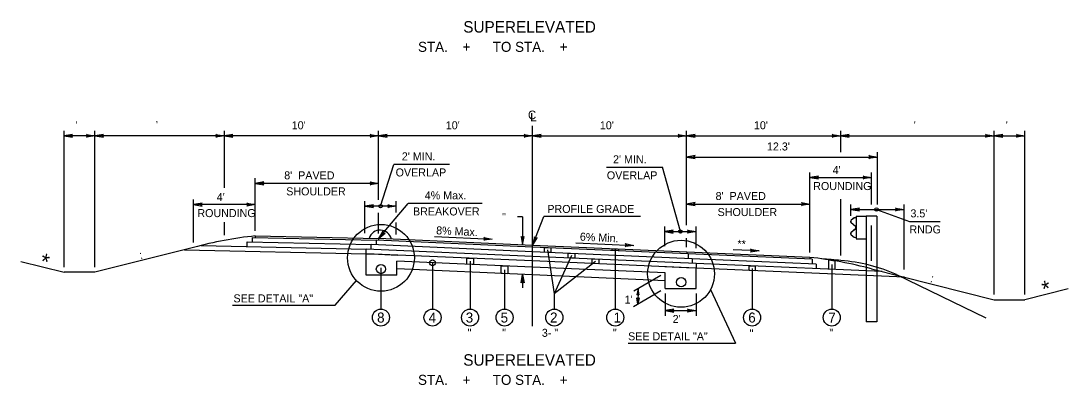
# Model space of a CAD drawing. Extents: x -592 to 1199, y -590 to 416.
# Drawn here: x 459.1 to 642.2, y 44 to 107.5 of the extents above; entities that cross this region are included whole.
import ezdxf

# ---------------------------------------------------------------- set-up
doc = ezdxf.new("R2010")
doc.units = 0
doc.layers.add('1', color=7, linetype='Continuous')
doc.layers.add('Des_ Drain_ Ftrs', color=7, linetype='Continuous')

msp = doc.modelspace()

# ---------------------------------------------------------------- linework, layer by layer
at = {"layer": '1'}
for p, q in [((466.61, 64.54), (466.61, 88.33)), ((471.99, 64.54), (471.99, 88.33)), ((494.66, 78.36), (494.66, 88.33)), ((521.6, 76.29), (521.6, 88.33)), ((548.54, 54.25), (548.54, 89.21)), ((575.48, 71.87), (575.48, 88.33)), ((602.42, 84.63), (602.42, 88.33)), ((629.25, 59.73), (629.25, 88.33)), ((634.64, 59.73), (634.64, 88.33)), ((471.99, 87.45), (466.61, 87.45)), ((494.66, 87.45), (471.99, 87.45)), ((521.6, 87.45), (494.66, 87.45)), ((548.54, 87.45), (521.6, 87.45)), ((548.54, 87.45), (575.48, 87.45)), ((575.48, 87.45), (602.42, 87.45)), ((602.42, 87.45), (629.25, 87.45)), ((629.25, 87.45), (634.64, 87.45)), ((608.85, 75.47), (608.85, 84.63)), ((521.97, 75.17), (524.25, 82.47)), ((534.01, 82.47), (524.25, 82.47)), ((575.48, 83.75), (608.85, 83.75)), ((561.49, 81.96), (571.25, 81.96)), ((574.38, 70.74), (571.25, 81.96)), ((597.04, 67.1), (597.04, 81.05)), ((607.81, 75.47), (607.81, 81.05)), ((500.05, 70.87), (500.05, 80.04)), ((521.6, 79.16), (500.05, 79.16)), ((597.04, 80.17), (607.81, 80.17)), ((489.27, 68.86), (489.27, 76.33)), ((500.05, 75.45), (489.27, 75.45)), ((519.23, 70.45), (519.23, 76.05)), ((524.71, 75.17), (519.23, 75.17)), ((521.59, 69.52), (526.78, 75.66)), ((524.71, 74.1), (524.71, 76.05)), ((539.71, 75.66), (526.78, 75.66)), ((575.48, 75.55), (597.04, 75.55)), ((602.42, 66.56), (602.42, 76.38)), ((604.16, 73.52), (604.16, 75.47)), ((613.54, 64.11), (613.54, 75.47)), ((521.6, 70.4), (521.6, 74.04)), ((546.79, 73.3), (545.91, 73.3)), ((546.79, 73.3), (546.79, 68.42)), ((548.55, 68.33), (550.51, 73.4)), ((567.42, 73.4), (550.51, 73.4)), ((604.16, 74.59), (613.54, 74.59)), ((605.11, 73.41), (605.11, 69.48)), ((605.11, 73.41), (606.85, 73.41)), ((606.85, 73.41), (606.85, 55.01)), ((608.75, 73.41), (606.85, 73.41)), ((608.68, 74.59), (614.44, 72.52)), ((608.75, 73.41), (608.75, 55.01)), ((494.66, 70.09), (494.66, 72.38)), ((524.71, 70.26), (524.71, 72.32)), ((571.64, 68.21), (571.64, 71.62)), ((577.12, 67.83), (577.12, 71.62)), ((604.23, 72.3), (604.99, 71.67)), ((604.78, 73.12), (604.24, 72.73)), ((604.25, 72.32), (605.01, 71.69)), ((604.79, 73.1), (604.26, 72.71)), ((605.11, 73.18), (604.78, 73.12)), ((605.11, 73.15), (604.79, 73.1)), ((605.08, 71.48), (605.08, 71.4)), ((605.11, 71.48), (605.11, 71.4)), ((607.81, 65.65), (607.81, 71.8)), ((614.44, 72.52), (619.79, 72.52)), ((499.55, 69.7), (521.25, 69.23)), ((499.55, 68.92), (499.55, 69.7)), ((500.05, 69.99), (521.59, 69.52)), ((500.05, 69.99), (500.05, 69.69)), ((531.37, 69.86), (541.48, 69.41)), ((571.64, 70.74), (577.12, 70.74)), ((575.48, 68.04), (575.48, 69.61)), ((604.99, 71.22), (604.23, 70.58)), ((604.24, 70.15), (604.78, 69.76)), ((605.01, 71.19), (604.25, 70.56)), ((604.26, 70.17), (604.79, 69.79)), ((604.78, 69.76), (605.11, 69.7)), ((604.79, 69.79), (605.11, 69.73)), ((489.27, 67.98), (471.99, 63.66)), ((490.6, 68.32), (519.41, 67.69)), ((498.63, 68.94), (520.33, 68.46)), ((498.63, 68.15), (498.63, 68.94)), ((548.54, 67.23), (520.33, 68.46)), ((520.33, 67.65), (520.33, 68.46)), ((548.54, 68.04), (521.25, 69.23)), ((521.25, 68.42), (521.25, 69.23)), ((548.54, 68.34), (521.59, 69.52)), ((521.59, 69.52), (521.59, 69.22)), ((575.49, 67.16), (548.54, 68.34)), ((575.72, 66.85), (548.54, 68.04)), ((556.11, 68.77), (566.22, 68.33)), ((605.11, 69.48), (606.85, 69.48)), ((487.68, 67.58), (519.41, 66.88)), ((548.54, 66.42), (519.41, 67.69)), ((519.41, 66.88), (519.41, 67.69)), ((519.41, 63.13), (519.41, 66.88)), ((548.54, 65.61), (519.41, 66.88)), ((519.41, 66.88), (521.6, 66.79)), ((521.6, 66.79), (524.89, 66.65)), ((576.43, 66.01), (548.54, 67.23)), ((577.13, 65.17), (548.54, 66.42)), ((551.17, 67.53), (552.34, 59.9)), ((555.35, 66.55), (552.34, 59.9)), ((563, 67.55), (563, 57.22)), ((597.04, 66.22), (575.49, 67.16)), ((575.49, 67.16), (575.49, 66.86)), ((597.43, 65.91), (575.72, 66.85)), ((575.72, 66.85), (575.72, 66.04)), ((598.13, 65.07), (576.43, 66.01)), ((576.43, 66.01), (576.43, 65.2)), ((588.13, 67.36), (583.64, 67.55)), ((597.04, 66.22), (597.04, 65.92)), ((459.07, 65.54), (466.61, 63.66)), ((522.02, 64.44), (522.02, 57.22)), ((522.03, 64.44), (522.03, 64.44)), ((548.54, 64.53), (524.8, 65.57)), ((524.8, 63.13), (524.8, 65.57)), ((548.54, 63.19), (524.8, 64.22)), ((531.04, 65.3), (531.04, 57.22)), ((537.6, 65.55), (537.6, 57.22)), ((577.13, 64.36), (548.54, 65.61)), ((571.74, 63.52), (548.54, 64.53)), ((559.53, 65.53), (552.34, 59.9)), ((575.48, 64.44), (571.64, 64.6)), ((577.13, 64.36), (575.48, 64.44)), ((577.13, 65.17), (577.13, 64.36)), ((609.65, 63.75), (577.13, 65.17)), ((577.13, 60.83), (577.13, 64.36)), ((613.57, 62.77), (577.13, 64.36)), ((586.92, 64.3), (586.92, 57.22)), ((597.43, 65.91), (597.43, 65.1)), ((598.13, 65.07), (598.13, 64.26)), ((600.85, 64.97), (600.85, 57.22)), ((604.16, 65.46), (604.16, 65.46)), ((607.81, 64.21), (629.25, 58.85)), ((471.99, 63.66), (466.61, 63.66)), ((524.8, 63.13), (519.41, 63.13)), ((543.64, 64.08), (543.64, 57.22)), ((546.79, 63.26), (546.79, 60.9)), ((571.74, 62.17), (548.54, 63.19)), ((570.98, 63.08), (566.22, 60.33)), ((571.74, 60.83), (571.74, 63.52)), ((571.74, 63.52), (571.74, 63.52)), ((612.16, 63.23), (627.78, 55.7)), ((513.99, 57.88), (517.73, 62.2)), ((566.98, 60.77), (566.96, 58.07)), ((571.74, 60.83), (577.13, 60.83)), ((579.66, 60.65), (584.01, 51.25)), ((642.17, 60.74), (634.64, 58.85)), ((552.34, 59.9), (552.34, 57.22)), ((570.98, 60.39), (566.21, 57.63)), ((571.74, 59.95), (571.74, 56.06)), ((577.13, 59.95), (577.13, 56.06)), ((629.25, 58.85), (634.64, 58.85)), ((496.06, 57.88), (513.99, 57.88)), ((571.74, 56.94), (577.13, 56.94)), ((608.75, 55.01), (606.85, 55.01)), ((565.23, 51.25), (584.01, 51.25))]:
    msp.add_line(p, q, dxfattribs=at)
for points in [[(550.6, 67.95), (551.75, 67.9), (551.75, 67.09), (550.6, 67.14)], [(537.03, 66.12), (538.18, 66.07), (538.18, 64.99), (537.03, 65.04)], [(554.78, 66.96), (555.92, 66.91), (555.92, 66.1), (554.78, 66.15)], [(560.1, 65.92), (560.1, 65.11), (558.95, 65.16), (558.95, 65.97)], [(562.43, 67.73), (563.57, 67.68), (563.57, 67.38), (562.43, 67.43)], [(543.07, 64.77), (544.21, 64.72), (544.21, 63.38), (543.07, 63.43)], [(586.4, 64.77), (587.44, 64.72), (587.44, 63.91), (586.4, 63.96)], [(600.33, 65.8), (601.38, 65.63), (601.38, 64.11), (600.33, 64.16)]]:
    msp.add_lwpolyline(points, close=True, dxfattribs=at)
for centre, radius in [((521.97, 75.17), 0.3), ((522.02, 66.16), 5.84), ((574.38, 70.74), 0.3), ((574.5, 63.38), 5.84), ((522.02, 64.2), 0.808), ((531.04, 65.3), 0.5), ((574.52, 61.9), 0.808), ((522.02, 55.73), 1.49), ((531.04, 55.73), 1.49), ((537.6, 55.73), 1.49), ((543.64, 55.73), 1.49), ((552.34, 55.73), 1.49), ((563, 55.73), 1.49), ((586.92, 55.73), 1.49), ((600.85, 55.73), 1.49)]:
    msp.add_circle(centre, radius, dxfattribs=at)
for centre, radius, start, end in [((506.94, 3.15), 67.19, 95.8911, 105.2497), ((521.89, 69), 2, 12.0711, 163.8353), ((590.15, -0.61), 67.19, 74.7602, 84.1188)]:
    msp.add_arc(centre, radius, start, end, dxfattribs=at)
msp.add_ellipse((608.68, 74.59), major_axis=(-0.311, 0), ratio=0.964041, dxfattribs=at)
for centre, major_axis, start_param, end_param in [((604.42, 72.51), (-0.288, 0), 5.35781, 7.138763), ((604.42, 72.51), (-0.258, 0), 5.35781, 7.138763), ((604.82, 71.48), (0.258, 0), 0, 0.855848), ((604.82, 71.48), (0.288, 0), 0, 0.855848), ((604.42, 70.37), (-0.288, 0), 5.427608, 7.208561), ((604.42, 70.37), (-0.258, 0), 5.427608, 7.208561), ((604.82, 71.4), (0.258, 0), 5.427337, 6.283185), ((604.82, 71.4), (0.288, 0), 5.427337, 6.283185), ((591.2, -34.98), (105.02, 0), 1.463691, 1.495354), ((600.23, 38.4), (28.39, 0), 1.136862, 1.493152)]:
    msp.add_ellipse(centre, major_axis=major_axis, ratio=0.964041, start_param=start_param, end_param=end_param, dxfattribs=at)
at = {"layer": 'Des_ Drain_ Ftrs'}
for points in [[(466.61, 87.45), (468.09, 87.2), (467.8, 87.45), (468.09, 87.7)], [(471.99, 87.45), (470.51, 87.2), (470.8, 87.45), (470.51, 87.7)], [(471.99, 87.45), (473.48, 87.2), (473.19, 87.45), (473.48, 87.7)], [(494.66, 87.45), (493.17, 87.2), (493.47, 87.45), (493.17, 87.7)], [(494.66, 87.45), (496.15, 87.2), (495.85, 87.45), (496.15, 87.7)], [(521.6, 87.45), (520.11, 87.2), (520.41, 87.45), (520.11, 87.7)], [(521.6, 87.45), (523.09, 87.2), (522.79, 87.45), (523.09, 87.7)], [(548.54, 87.45), (547.05, 87.2), (547.35, 87.45), (547.05, 87.7)], [(548.54, 87.45), (550.03, 87.2), (549.74, 87.45), (550.03, 87.7)], [(575.48, 87.45), (573.99, 87.2), (574.29, 87.45), (573.99, 87.7)], [(575.48, 87.45), (576.97, 87.2), (576.68, 87.45), (576.97, 87.7)], [(602.42, 87.45), (600.94, 87.2), (601.23, 87.45), (600.94, 87.7)], [(602.42, 87.45), (603.91, 87.2), (603.62, 87.45), (603.91, 87.7)], [(629.25, 87.45), (627.76, 87.2), (628.05, 87.45), (627.76, 87.7)], [(629.25, 87.45), (630.74, 87.2), (630.44, 87.45), (630.74, 87.7)], [(634.64, 87.45), (633.15, 87.2), (633.44, 87.45), (633.15, 87.7)], [(575.48, 83.75), (576.97, 83.5), (576.68, 83.75), (576.97, 84)], [(608.85, 83.75), (607.36, 83.5), (607.66, 83.75), (607.36, 84)], [(500.05, 79.16), (501.54, 78.91), (501.24, 79.16), (501.54, 79.41)], [(521.6, 79.16), (520.11, 78.91), (520.41, 79.16), (520.11, 79.41)], [(597.04, 80.17), (598.52, 79.93), (598.23, 80.17), (598.52, 80.42)], [(607.81, 80.17), (606.32, 79.93), (606.62, 80.17), (606.32, 80.42)], [(489.27, 75.45), (490.76, 75.2), (490.46, 75.45), (490.76, 75.7)], [(500.05, 75.45), (498.56, 75.2), (498.85, 75.45), (498.56, 75.7)], [(519.23, 75.17), (520.71, 74.92), (520.42, 75.17), (520.71, 75.41)], [(524.71, 75.17), (523.22, 74.92), (523.52, 75.17), (523.22, 75.41)], [(575.48, 75.55), (576.97, 75.3), (576.68, 75.55), (576.97, 75.79)], [(597.04, 75.55), (595.55, 75.3), (595.84, 75.55), (595.55, 75.79)], [(604.16, 74.59), (605.7, 74.34), (605.4, 74.59), (605.7, 74.84)], [(613.54, 74.59), (612, 74.34), (612.31, 74.59), (612, 74.84)], [(521.59, 69.52), (522.74, 70.49), (522.36, 70.43), (522.36, 70.81)], [(541.48, 69.41), (539.99, 69.23), (540.29, 69.47), (540.01, 69.73)], [(546.79, 68.42), (547.04, 69.91), (546.79, 69.61), (546.54, 69.91)], [(548.55, 68.33), (549.32, 69.64), (548.98, 69.45), (548.85, 69.81)], [(571.64, 70.74), (573.13, 70.49), (572.83, 70.74), (573.13, 70.99)], [(577.12, 70.74), (575.64, 70.49), (575.93, 70.74), (575.64, 70.99)], [(566.22, 68.33), (564.72, 68.15), (565.03, 68.38), (564.74, 68.64)], [(588.13, 67.36), (586.63, 67.17), (586.94, 67.41), (586.66, 67.67)], [(546.79, 63.26), (547.04, 61.78), (546.79, 62.07), (546.54, 61.78)], [(566.98, 60.77), (566.79, 59.69), (566.98, 59.9), (567.16, 59.69)], [(566.96, 58.07), (566.79, 59.15), (566.97, 58.94), (567.15, 59.15)], [(571.74, 56.94), (573.23, 56.69), (572.93, 56.94), (573.23, 57.19)], [(577.13, 56.94), (575.64, 56.69), (575.94, 56.94), (575.64, 57.19)]]:
    msp.add_lwpolyline(points, close=True, dxfattribs=at)

# ---------------------------------------------------------------- texts
at = {"layer": '1'}
for s, height, p in [('SUPERELEVATED', 2, (536.42, 105.48)), ('STA.    +      TO STA.    +     ', 1.75, (528.51, 102.12)), (" '", 1.4, (468.11, 88.6)), ("  '", 1.4, (481.63, 88.67)), ("10'", 1.4, (506.42, 88.6)), ("10'", 1.4, (533.36, 88.6)), ("10'", 1.4, (560.3, 88.6)), ("10'", 1.4, (587.24, 88.6)), ("  '", 1.4, (614.14, 88.6)), (" '", 1.4, (630.75, 88.6)), ("12.3'", 1.4, (589.52, 84.9)), ("2' MIN.", 1.4, (525.67, 83.17)), ("2' MIN.", 1.4, (562.61, 82.66)), ("8'  PAVED", 1.4, (505.11, 79.86)), ('OVERLAP', 1.4, (524.59, 80.37)), ('OVERLAP', 1.4, (561.52, 79.86)), ("4'", 1.4, (601, 80.79)), ('ROUNDING', 1.4, (597.61, 77.99)), ("4'", 1.4, (493.31, 76.07)), ('SHOULDER', 1.4, (505.46, 77.06)), ('4% Max.', 1.4, (529.68, 76.36)), ("8'  PAVED", 1.4, (580.54, 76.25)), ('PROFILE GRADE', 1.4, (551.12, 73.99)), ('ROUNDING', 1.4, (489.92, 73.27)), ('BREAKOVER', 1.4, (527.63, 73.56)), ('SHOULDER', 1.4, (580.89, 73.45)), ("3.5'", 1.4, (614.61, 73.22)), ('RNDG', 1.4, (614.43, 70.42)), ('SEE DETAIL "A"', 1.4, (496.24, 58.38)), ('8', 1.75, (521.35, 54.86)), ('4', 1.75, (530.37, 54.86)), ('3', 1.75, (536.85, 54.86)), ('5', 1.75, (542.95, 54.86)), ('2', 1.75, (551.59, 54.86)), ('1', 1.75, (562.7, 54.86)), ("2'", 1.4, (573.03, 54.79)), ('6', 1.75, (586.25, 54.86)), ('7', 1.75, (600.26, 54.86)), (' "', 1.4, (536.66, 52.37)), (' "', 1.4, (542.7, 52.37)), ('3- "', 1.4, (550.16, 52.37)), (' "', 1.4, (562.06, 52.37)), ('SEE DETAIL "A"', 1.4, (565.24, 51.76)), (' "', 1.4, (585.97, 52.28)), (' "', 1.4, (599.91, 52.37)), ('SUPERELEVATED', 2, (536.42, 47.33)), ('STA.    +      TO STA.    +     ', 1.75, (528.51, 43.98))]:
    msp.add_text(s, height=height, dxfattribs=at).set_placement(p)
for s, height, rotation, p in [('  "', 1.4, 0.1438, (542.17, 72.59)), ('8% Max.', 1.4, 357.3762, (531.65, 70.27)), ('6% Min.', 1.4, 357.3732, (556.78, 69.17)), ('**', 1.4, 357.2166, (584.32, 67.92)), ('*', 2.8, 347.1521, (462.24, 64.3)), (' : ', 1.4, 14.2282, (479.45, 65.8)), (' : ', 1.4, 345.7718, (617.48, 62.08)), ('*', 2.8, 12.8479, (637.95, 59.26)), ("1'", 1.4, 0.1438, (564.64, 58.16))]:
    msp.add_text(s, height=height, rotation=rotation, dxfattribs=at).set_placement(p)
at = {"layer": 'Des_ Drain_ Ftrs'}
for s, p in [('C', (547.73, 90.36)), ('L', (548.12, 89.97))]:
    msp.add_text(s, height=1.5, dxfattribs=at).set_placement(p)

doc.saveas('drawing.dxf')
